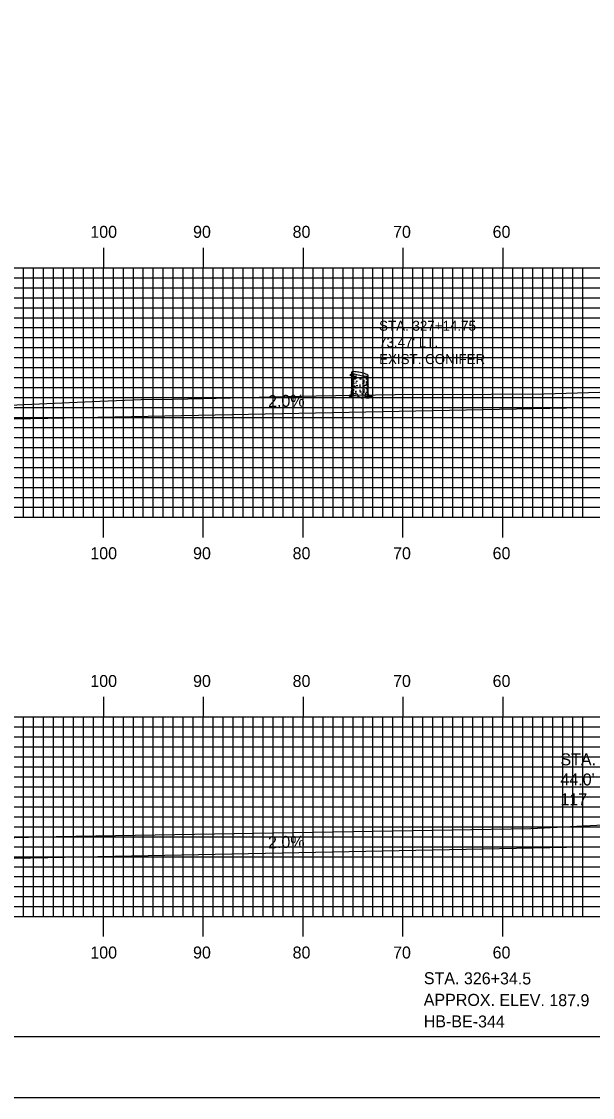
# Model space of a CAD drawing. Extents: x 1821605 to 1821948, y 442591 to 442811.
# Drawn here: x 1821662.5 to 1821719.7, y 442590.5 to 442698.3 of the extents above; entities that cross this region are included whole.
import ezdxf

# ---------------------------------------------------------------- set-up
doc = ezdxf.new("R2010")
doc.units = 0
for name, color, linetype in [('ANNOTATION', 7, 'Continuous'), ('BORDER', 7, 'Continuous'), ('BORING - NO REFUSAL', 7, 'Continuous'), ('D_Drainage_Text', 7, 'Continuous'), ('D_Text_Monospaced', 7, 'Continuous'), ('H_V ANNOTATION', 7, 'Continuous'), ('M_Trees_Conifer_Pay', 7, 'Continuous'), ('MAJOR', 7, 'Continuous'), ('MINOR', 7, 'Continuous'), ('PLOT BOUNDARY', 7, 'Continuous'), ('S_Roadway_Centerline', 7, 'Continuous')]:
    doc.layers.add(name, color=color, linetype=linetype)

msp = doc.modelspace()

# ---------------------------------------------------------------- linework, layer by layer
at = {"layer": 'ANNOTATION'}
for p, q in [((1821726.4, 442659.78), (1821630.74, 442657.87)), ((1821726.4, 442615.77), (1821630.74, 442613.85))]:
    msp.add_line(p, q, dxfattribs=at)
at = {"layer": 'BORDER'}
msp.add_lwpolyline([(1821621.14, 442596.67), (1821941.14, 442596.67), (1821941.14, 442806.67), (1821621.14, 442806.67)], close=True, dxfattribs=at)
at = {"layer": 'M_Trees_Conifer_Pay'}
for p, q in [((1821695.61, 442661.55), (1821695.61, 442663.2)), ((1821695.68, 442663.13), (1821695.68, 442662.97)), ((1821695.68, 442662.9), (1821695.68, 442662.77)), ((1821695.68, 442662.58), (1821695.68, 442662.25)), ((1821695.68, 442662.21), (1821695.68, 442662.05)), ((1821695.74, 442662.57), (1821695.79, 442662.51)), ((1821695.8, 442663.07), (1821695.8, 442662.85)), ((1821695.8, 442662.76), (1821695.8, 442662.71)), ((1821695.8, 442662.37), (1821695.8, 442662.24)), ((1821695.8, 442662.13), (1821695.8, 442662.02)), ((1821696.03, 442662.87), (1821696.03, 442662.67)), ((1821696.03, 442662.62), (1821696.03, 442662.53)), ((1821696.03, 442662.18), (1821696.03, 442662.07)), ((1821696.42, 442662.6), (1821696.42, 442662.5)), ((1821696.82, 442662.83), (1821696.82, 442662.66)), ((1821696.82, 442662.43), (1821696.82, 442662.19)), ((1821697.04, 442662.81), (1821697.04, 442662.58)), ((1821697.04, 442662.54), (1821697.04, 442662.46)), ((1821697.04, 442662.06), (1821697.04, 442661.92)), ((1821697.17, 442662.82), (1821697.17, 442662.72)), ((1821697.17, 442662.65), (1821697.17, 442662.44)), ((1821697.17, 442662.38), (1821697.17, 442662.18)), ((1821697.17, 442662.14), (1821697.17, 442661.8)), ((1821697.22, 442662.83), (1821697.22, 442662.36)), ((1821697.22, 442662.29), (1821697.22, 442661.99)), ((1821697.27, 442661.14), (1821697.27, 442662.87)), ((1821695.68, 442662), (1821695.68, 442661.79)), ((1821695.68, 442661.75), (1821695.68, 442661.68)), ((1821695.68, 442661.64), (1821695.68, 442661.47)), ((1821695.8, 442661.89), (1821695.8, 442661.74)), ((1821695.8, 442661.52), (1821695.8, 442661.34)), ((1821696.03, 442661.71), (1821696.03, 442661.56)), ((1821696.03, 442661.33), (1821696.03, 442661.24)), ((1821696.42, 442661.99), (1821696.42, 442661.91)), ((1821696.42, 442661.89), (1821696.42, 442661.74)), ((1821696.42, 442661.45), (1821696.42, 442661.29)), ((1821696.82, 442661.94), (1821696.82, 442661.79)), ((1821696.82, 442661.75), (1821696.82, 442661.58)), ((1821696.82, 442661.3), (1821696.82, 442661.14)), ((1821697.04, 442661.65), (1821697.04, 442661.51)), ((1821697.04, 442661.25), (1821697.04, 442661.15)), ((1821697.17, 442661.75), (1821697.17, 442661.61)), ((1821697.17, 442661.51), (1821697.17, 442661.13)), ((1821697.22, 442661.94), (1821697.22, 442661.45)), ((1821697.22, 442661.39), (1821697.22, 442661.14)), ((1821696.6, 442660.69), (1821696.73, 442660.75)), ((1821697.04, 442660.75), (1821696.88, 442660.82))]:
    msp.add_line(p, q, dxfattribs=at)
for points in [[(1821695.56, 442662.93), (1821695.49, 442662.94), (1821695.41, 442662.84)], [(1821695.79, 442662.7), (1821695.75, 442662.63), (1821695.71, 442662.68), (1821695.65, 442662.75), (1821695.56, 442662.94), (1821695.49, 442662.99), (1821695.46, 442663)], [(1821695.78, 442662.45), (1821695.74, 442662.57), (1821695.68, 442662.69), (1821695.65, 442662.76), (1821695.58, 442662.9)], [(1821695.82, 442662.66), (1821695.86, 442662.58), (1821695.86, 442662.51), (1821695.83, 442662.45)], [(1821697.09, 442662.17), (1821697.1, 442662.27), (1821697.06, 442662.24), (1821697.06, 442662.15)], [(1821695.61, 442661.55), (1821695.56, 442661.29), (1821695.54, 442661.02), (1821695.48, 442660.89), (1821695.35, 442660.86), (1821695.58, 442660.83), (1821695.58, 442660.83), (1821695.57, 442660.78), (1821695.32, 442660.68), (1821695.6, 442660.7), (1821695.95, 442660.72), (1821696.28, 442660.71), (1821696.27, 442660.79), (1821696.42, 442660.71), (1821696.6, 442660.69), (1821696.58, 442660.62), (1821696.85, 442660.66), (1821697.07, 442660.64), (1821697.36, 442660.65), (1821697.07, 442660.71), (1821697.04, 442660.75), (1821697.2, 442660.81), (1821697.44, 442660.82), (1821697.68, 442660.82), (1821697.34, 442660.88), (1821697.3, 442660.96), (1821697.27, 442661.14)], [(1821695.78, 442661.27), (1821695.71, 442661.16), (1821695.7, 442660.99), (1821695.58, 442660.83)], [(1821695.68, 442661.41), (1821695.68, 442661.27), (1821695.63, 442661.2), (1821695.62, 442661)], [(1821695.74, 442660.77), (1821695.75, 442660.91), (1821695.83, 442661.04)], [(1821695.95, 442661.77), (1821695.94, 442661.7), (1821695.89, 442661.71), (1821695.91, 442661.87)], [(1821696.02, 442661.16), (1821696.01, 442661.04), (1821695.93, 442660.99)], [(1821696.27, 442660.79), (1821696.19, 442660.93), (1821696.18, 442661.04)], [(1821696.76, 442660.86), (1821696.69, 442660.96), (1821696.66, 442661.1)], [(1821696.98, 442661.1), (1821696.98, 442660.97), (1821697.07, 442660.87)], [(1821697.15, 442661.08), (1821697.14, 442660.96), (1821697.19, 442660.87), (1821697.2, 442660.81)], [(1821697.22, 442661.1), (1821697.25, 442661.02), (1821697.27, 442660.93)]]:
    msp.add_lwpolyline(points, dxfattribs=at)
for centre, radius, start, end in [((1821695.63, 442663.2), 0.0264, 145.7806, 156.5926), ((1821695.64, 442663.2), 0.0314, 133.077, 145.7806), ((1821695.63, 442663.2), 0.0226, 156.5926, 168.2806), ((1821695.63, 442663.2), 0.0226, 168.2806, 179.9685), ((1821695.64, 442663.2), 0.0314, 190.7806, 203.4842), ((1821695.63, 442663.2), 0.0264, 179.9685, 190.7806), ((1821695.66, 442663.21), 0.0527, 203.4842, 213.2806), ((1821695.68, 442663.23), 0.0817, 213.2806, 227.6113), ((1821695.67, 442663.16), 0.0817, 108.9499, 123.2806), ((1821695.65, 442663.18), 0.0527, 123.2806, 133.077), ((1821695.8, 442663.35), 0.251, 227.6113, 235.7806), ((1821695.72, 442663), 0.251, 100.7806, 108.9499), ((1821696.11, 442663.81), 0.802, 235.7806, 251.9406), ((1821695.83, 442662.46), 0.802, 84.6206, 100.7806), ((1821695.42, 442658.1), 5.18, 78.2806, 84.6206), ((1821695.42, 442658.1), 5.18, 71.9406, 78.2806), ((1821695.65, 442663.08), 0.0441, 196.0515, 210), ((1821695.64, 442663.08), 0.0334, 185.7849, 196.0515), ((1821695.67, 442663.09), 0.0624, 210, 228.7494), ((1821695.64, 442662.92), 0.0334, 185.7849, 196.0515), ((1821695.65, 442662.92), 0.0441, 196.0515, 210), ((1821695.67, 442662.93), 0.0624, 210, 228.7494), ((1821695.64, 442662.48), 0.0334, 185.7849, 196.0515), ((1821695.64, 442662.24), 0.0334, 185.7849, 196.0515), ((1821695.65, 442662.24), 0.0441, 196.0515, 210), ((1821695.67, 442662.25), 0.0624, 210, 228.7494), ((1821695.64, 442662.03), 0.0334, 185.7849, 196.0515), ((1821695.65, 442662.03), 0.0441, 196.0515, 210), ((1821695.67, 442662.04), 0.0624, 210, 228.7494), ((1821695.74, 442663.17), 0.172, 228.7494, 240), ((1821695.74, 442663.02), 0.172, 228.7494, 240), ((1821695.74, 442662.34), 0.172, 228.7494, 240), ((1821695.94, 442663.36), 0.571, 240, 242.9763), ((1821695.94, 442662.68), 0.571, 240, 242.8104), ((1821695.94, 442662.92), 0.571, 242.9571, 255.5507), ((1821695.94, 442663.52), 0.571, 247.5868, 255.5683), ((1821695.94, 442662.68), 0.571, 253.0704, 261.8968), ((1821695.94, 442663.36), 0.571, 255.6333, 261.8968), ((1821697.46, 442667.97), 5.18, 251.9406, 258.2806), ((1821696.44, 442666.88), 4.12, 261.8968, 263.762), ((1821696.44, 442666.2), 4.12, 261.8968, 262.3875), ((1821696.44, 442666.65), 4.12, 262.9442, 264.2151), ((1821696.44, 442666.43), 4.12, 264.0496, 266.2948), ((1821697.46, 442667.97), 5.18, 258.2806, 264.6206), ((1821696.44, 442666.65), 4.12, 269.6419, 270), ((1821696.44, 442666.65), 4.12, 270, 271.9249), ((1821696.44, 442666.88), 4.12, 273.2669, 275.3045), ((1821696.44, 442666.2), 4.12, 273.3324, 275.919), ((1821697.05, 442663.61), 0.802, 264.6206, 280.7806), ((1821696.77, 442662.26), 0.802, 55.7806, 71.9406), ((1821696.94, 442663.13), 0.571, 282.0154, 293.1403), ((1821696.94, 442662.92), 0.571, 292.9413, 300), ((1821697.16, 442663.07), 0.251, 280.7806, 288.9499), ((1821697.08, 442662.72), 0.251, 47.6113, 55.7806), ((1821696.94, 442663.13), 0.571, 299.6633, 300), ((1821696.94, 442662.68), 0.571, 299.6633, 300), ((1821697.14, 442662.78), 0.172, 300, 311.2506), ((1821697.14, 442662.34), 0.172, 300, 311.2506), ((1821697.21, 442662.91), 0.0817, 288.9499, 303.2806), ((1821697.2, 442662.84), 0.0817, 33.2806, 47.6113), ((1821697.21, 442662.7), 0.0624, 311.2506, 330), ((1821697.21, 442662.25), 0.0624, 311.2506, 330), ((1821697.21, 442662.04), 0.0624, 311.2506, 330), ((1821697.24, 442662.87), 0.0314, 313.077, 325.7806), ((1821697.23, 442662.89), 0.0527, 303.2806, 313.077), ((1821697.22, 442662.86), 0.0527, 23.4842, 33.2806), ((1821697.24, 442662.87), 0.0314, 10.7806, 23.4842), ((1821697.25, 442662.87), 0.0264, 359.9685, 10.7806), ((1821697.25, 442662.87), 0.0226, 348.2806, 359.9685), ((1821697.25, 442662.87), 0.0226, 336.5926, 348.2806), ((1821697.25, 442662.87), 0.0264, 325.7806, 336.5926), ((1821697.24, 442662.69), 0.0334, 0, 16.0515), ((1821697.24, 442662.69), 0.0334, 343.9485, 360), ((1821697.23, 442662.69), 0.0441, 330, 343.9485), ((1821697.24, 442662.24), 0.0334, 0, 16.0515), ((1821697.24, 442662.24), 0.0334, 343.9485, 360), ((1821697.23, 442662.24), 0.0441, 330, 343.9485), ((1821697.24, 442662.03), 0.0334, 0, 16.0515), ((1821697.24, 442662.03), 0.0334, 343.9485, 360), ((1821697.23, 442662.03), 0.0441, 330, 343.9485), ((1821695.65, 442661.6), 0.0441, 196.0515, 210), ((1821695.64, 442661.6), 0.0334, 185.7849, 196.0515), ((1821695.67, 442661.61), 0.0624, 210, 228.7494), ((1821695.64, 442661.18), 0.0334, 185.7849, 196.0515), ((1821695.65, 442661.18), 0.0441, 196.0515, 210), ((1821695.67, 442661.19), 0.0624, 210, 228.7494), ((1821695.74, 442662.13), 0.172, 228.7494, 240), ((1821695.74, 442661.69), 0.172, 228.7494, 240), ((1821695.74, 442661.28), 0.172, 228.7494, 240), ((1821695.94, 442662.47), 0.571, 240, 242.8104), ((1821695.94, 442662.04), 0.571, 240, 250.7093), ((1821695.94, 442662.23), 0.571, 242.8104, 254.6017), ((1821695.94, 442661.84), 0.571, 242.7279, 251.4933), ((1821695.94, 442661.62), 0.571, 258.363, 261.8968), ((1821696.44, 442665.14), 4.12, 261.8968, 262.6316), ((1821696.44, 442665.36), 4.12, 263.2104, 264.2151), ((1821696.44, 442665.99), 4.12, 264.5431, 266.8507), ((1821696.44, 442665.99), 4.12, 269.6419, 270), ((1821696.44, 442665.36), 4.12, 269.8672, 270), ((1821696.44, 442665.36), 4.12, 270, 272.1883), ((1821696.44, 442665.75), 4.12, 273.6807, 275.284), ((1821696.44, 442665.55), 4.12, 274.1603, 276.5009), ((1821696.44, 442665.14), 4.12, 276.488, 277.5562), ((1821696.44, 442665.99), 4.12, 276.8526, 278.1032), ((1821696.94, 442662.47), 0.571, 278.1032, 280.7293), ((1821696.94, 442662.47), 0.571, 293.1403, 300), ((1821696.94, 442662.23), 0.571, 293.1403, 300), ((1821696.95, 442662.04), 0.571, 291.9732, 298.7631), ((1821696.94, 442661.84), 0.571, 293.1403, 300), ((1821696.94, 442661.62), 0.571, 295.4686, 300), ((1821697.14, 442662.13), 0.172, 300, 311.2506), ((1821697.14, 442661.89), 0.172, 300, 311.2506), ((1821697.14, 442661.5), 0.172, 300, 311.2506), ((1821697.14, 442661.28), 0.172, 300, 311.2506), ((1821697.21, 442661.81), 0.0624, 311.2506, 330), ((1821697.21, 442661.41), 0.0624, 311.2506, 330), ((1821697.21, 442661.19), 0.0624, 311.2506, 330), ((1821697.24, 442661.79), 0.0334, 0, 16.0515), ((1821697.24, 442661.79), 0.0334, 343.9485, 360), ((1821697.23, 442661.8), 0.0441, 330, 343.9485), ((1821697.24, 442661.6), 0.0334, 0, 16.0515), ((1821697.24, 442661.4), 0.0334, 0, 16.0515), ((1821697.24, 442661.4), 0.0334, 343.9485, 360), ((1821697.23, 442661.4), 0.0441, 330, 343.9485), ((1821697.24, 442661.18), 0.0334, 0, 16.0515), ((1821697.24, 442661.18), 0.0334, 343.9485, 360), ((1821697.23, 442661.18), 0.0441, 330, 343.9485)]:
    msp.add_arc(centre, radius, start, end, dxfattribs=at)
at = {"layer": 'MAJOR'}
for p, q in [((1821670.74, 442675.67), (1821670.74, 442673.67)), ((1821680.74, 442675.67), (1821680.74, 442673.67)), ((1821690.74, 442675.67), (1821690.74, 442673.67)), ((1821700.74, 442675.67), (1821700.74, 442673.67)), ((1821710.74, 442675.67), (1821710.74, 442673.67)), ((1821630.74, 442673.67), (1821910.74, 442673.67)), ((1821630.74, 442673.67), (1821910.74, 442673.67)), ((1821670.74, 442648.67), (1821670.74, 442673.67)), ((1821680.74, 442648.67), (1821680.74, 442673.67)), ((1821690.74, 442648.67), (1821690.74, 442673.67)), ((1821700.74, 442648.67), (1821700.74, 442673.67)), ((1821710.74, 442648.67), (1821710.74, 442673.67)), ((1821630.74, 442668.67), (1821910.74, 442668.67)), ((1821630.74, 442663.67), (1821910.74, 442663.67)), ((1821630.74, 442658.67), (1821910.74, 442658.67)), ((1821630.74, 442653.67), (1821910.74, 442653.67)), ((1821630.74, 442648.67), (1821910.74, 442648.67)), ((1821630.74, 442648.67), (1821910.74, 442648.67)), ((1821670.74, 442646.66), (1821670.74, 442648.67)), ((1821680.74, 442646.66), (1821680.74, 442648.67)), ((1821690.74, 442646.66), (1821690.74, 442648.67)), ((1821700.74, 442646.66), (1821700.74, 442648.67)), ((1821710.74, 442646.66), (1821710.74, 442648.67)), ((1821670.74, 442630.67), (1821670.74, 442628.67)), ((1821680.74, 442630.67), (1821680.74, 442628.67)), ((1821690.74, 442630.67), (1821690.74, 442628.67)), ((1821700.74, 442630.67), (1821700.74, 442628.67)), ((1821710.74, 442630.67), (1821710.74, 442628.67)), ((1821630.74, 442628.67), (1821910.74, 442628.67)), ((1821630.74, 442628.67), (1821910.74, 442628.67)), ((1821670.74, 442608.67), (1821670.74, 442628.67)), ((1821680.74, 442608.67), (1821680.74, 442628.67)), ((1821690.74, 442608.67), (1821690.74, 442628.67)), ((1821700.74, 442608.67), (1821700.74, 442628.67)), ((1821710.74, 442608.67), (1821710.74, 442628.67)), ((1821630.74, 442623.67), (1821910.74, 442623.67)), ((1821630.74, 442618.67), (1821910.74, 442618.67)), ((1821630.74, 442613.67), (1821910.74, 442613.67)), ((1821630.74, 442608.67), (1821910.74, 442608.67)), ((1821630.74, 442608.67), (1821910.74, 442608.67)), ((1821670.74, 442606.66), (1821670.74, 442608.67)), ((1821680.74, 442606.66), (1821680.74, 442608.67)), ((1821690.74, 442606.66), (1821690.74, 442608.67)), ((1821700.74, 442606.66), (1821700.74, 442608.67)), ((1821710.74, 442606.66), (1821710.74, 442608.67))]:
    msp.add_line(p, q, dxfattribs=at)
at = {"layer": 'MINOR'}
for p, q in [((1821662.74, 442648.67), (1821662.74, 442673.67)), ((1821663.74, 442648.67), (1821663.74, 442673.67)), ((1821664.74, 442648.67), (1821664.74, 442673.67)), ((1821665.74, 442648.67), (1821665.74, 442673.67)), ((1821666.74, 442648.67), (1821666.74, 442673.67)), ((1821667.74, 442648.67), (1821667.74, 442673.67)), ((1821668.74, 442648.67), (1821668.74, 442673.67)), ((1821669.74, 442648.67), (1821669.74, 442673.67)), ((1821671.74, 442648.67), (1821671.74, 442673.67)), ((1821672.74, 442648.67), (1821672.74, 442673.67)), ((1821673.74, 442648.67), (1821673.74, 442673.67)), ((1821674.74, 442648.67), (1821674.74, 442673.67)), ((1821675.74, 442648.67), (1821675.74, 442673.67)), ((1821676.74, 442648.67), (1821676.74, 442673.67)), ((1821677.74, 442648.67), (1821677.74, 442673.67)), ((1821678.74, 442648.67), (1821678.74, 442673.67)), ((1821679.74, 442648.67), (1821679.74, 442673.67)), ((1821681.74, 442648.67), (1821681.74, 442673.67)), ((1821682.74, 442648.67), (1821682.74, 442673.67)), ((1821683.74, 442648.67), (1821683.74, 442673.67)), ((1821684.74, 442648.67), (1821684.74, 442673.67)), ((1821685.74, 442648.67), (1821685.74, 442673.67)), ((1821686.74, 442648.67), (1821686.74, 442673.67)), ((1821687.74, 442648.67), (1821687.74, 442673.67)), ((1821688.74, 442648.67), (1821688.74, 442673.67)), ((1821689.74, 442648.67), (1821689.74, 442673.67)), ((1821691.74, 442648.67), (1821691.74, 442673.67)), ((1821692.74, 442648.67), (1821692.74, 442673.67)), ((1821693.74, 442648.67), (1821693.74, 442673.67)), ((1821694.74, 442648.67), (1821694.74, 442673.67)), ((1821695.74, 442648.67), (1821695.74, 442673.67)), ((1821696.74, 442648.67), (1821696.74, 442673.67)), ((1821697.74, 442648.67), (1821697.74, 442673.67)), ((1821698.74, 442648.67), (1821698.74, 442673.67)), ((1821699.74, 442648.67), (1821699.74, 442673.67)), ((1821701.74, 442648.67), (1821701.74, 442673.67)), ((1821702.74, 442648.67), (1821702.74, 442673.67)), ((1821703.74, 442648.67), (1821703.74, 442673.67)), ((1821704.74, 442648.67), (1821704.74, 442673.67)), ((1821705.74, 442648.67), (1821705.74, 442673.67)), ((1821706.74, 442648.67), (1821706.74, 442673.67)), ((1821707.74, 442648.67), (1821707.74, 442673.67)), ((1821708.74, 442648.67), (1821708.74, 442673.67)), ((1821709.74, 442648.67), (1821709.74, 442673.67)), ((1821711.74, 442648.67), (1821711.74, 442673.67)), ((1821712.74, 442648.67), (1821712.74, 442673.67)), ((1821713.74, 442648.67), (1821713.74, 442673.67)), ((1821714.74, 442648.67), (1821714.74, 442673.67)), ((1821715.74, 442648.67), (1821715.74, 442673.67)), ((1821716.74, 442648.67), (1821716.74, 442673.67)), ((1821717.74, 442648.67), (1821717.74, 442673.67)), ((1821718.74, 442648.67), (1821718.74, 442673.67)), ((1821630.74, 442672.67), (1821910.74, 442672.67)), ((1821630.74, 442671.67), (1821910.74, 442671.67)), ((1821630.74, 442670.67), (1821910.74, 442670.67)), ((1821630.74, 442669.67), (1821910.74, 442669.67)), ((1821630.74, 442667.67), (1821910.74, 442667.67)), ((1821630.74, 442666.67), (1821910.74, 442666.67)), ((1821630.74, 442665.67), (1821910.74, 442665.67)), ((1821630.74, 442664.67), (1821910.74, 442664.67)), ((1821630.74, 442662.67), (1821910.74, 442662.67)), ((1821630.74, 442661.67), (1821910.74, 442661.67)), ((1821630.74, 442660.67), (1821910.74, 442660.67)), ((1821630.74, 442659.67), (1821910.74, 442659.67)), ((1821630.74, 442657.67), (1821910.74, 442657.67)), ((1821630.74, 442656.67), (1821910.74, 442656.67)), ((1821630.74, 442655.67), (1821910.74, 442655.67)), ((1821630.74, 442654.67), (1821910.74, 442654.67)), ((1821630.74, 442652.67), (1821910.74, 442652.67)), ((1821630.74, 442651.67), (1821910.74, 442651.67)), ((1821630.74, 442650.67), (1821910.74, 442650.67)), ((1821630.74, 442649.67), (1821910.74, 442649.67)), ((1821662.74, 442608.67), (1821662.74, 442628.67)), ((1821663.74, 442608.67), (1821663.74, 442628.67)), ((1821664.74, 442608.67), (1821664.74, 442628.67)), ((1821665.74, 442608.67), (1821665.74, 442628.67)), ((1821666.74, 442608.67), (1821666.74, 442628.67)), ((1821667.74, 442608.67), (1821667.74, 442628.67)), ((1821668.74, 442608.67), (1821668.74, 442628.67)), ((1821669.74, 442608.67), (1821669.74, 442628.67)), ((1821671.74, 442608.67), (1821671.74, 442628.67)), ((1821672.74, 442608.67), (1821672.74, 442628.67)), ((1821673.74, 442608.67), (1821673.74, 442628.67)), ((1821674.74, 442608.67), (1821674.74, 442628.67)), ((1821675.74, 442608.67), (1821675.74, 442628.67)), ((1821676.74, 442608.67), (1821676.74, 442628.67)), ((1821677.74, 442608.67), (1821677.74, 442628.67)), ((1821678.74, 442608.67), (1821678.74, 442628.67)), ((1821679.74, 442608.67), (1821679.74, 442628.67)), ((1821681.74, 442608.67), (1821681.74, 442628.67)), ((1821682.74, 442608.67), (1821682.74, 442628.67)), ((1821683.74, 442608.67), (1821683.74, 442628.67)), ((1821684.74, 442608.67), (1821684.74, 442628.67)), ((1821685.74, 442608.67), (1821685.74, 442628.67)), ((1821686.74, 442608.67), (1821686.74, 442628.67)), ((1821687.74, 442608.67), (1821687.74, 442628.67)), ((1821688.74, 442608.67), (1821688.74, 442628.67)), ((1821689.74, 442608.67), (1821689.74, 442628.67)), ((1821691.74, 442608.67), (1821691.74, 442628.67)), ((1821692.74, 442608.67), (1821692.74, 442628.67)), ((1821693.74, 442608.67), (1821693.74, 442628.67)), ((1821694.74, 442608.67), (1821694.74, 442628.67)), ((1821695.74, 442608.67), (1821695.74, 442628.67)), ((1821696.74, 442608.67), (1821696.74, 442628.67)), ((1821697.74, 442608.67), (1821697.74, 442628.67)), ((1821698.74, 442608.67), (1821698.74, 442628.67)), ((1821699.74, 442608.67), (1821699.74, 442628.67)), ((1821701.74, 442608.67), (1821701.74, 442628.67)), ((1821702.74, 442608.67), (1821702.74, 442628.67)), ((1821703.74, 442608.67), (1821703.74, 442628.67)), ((1821704.74, 442608.67), (1821704.74, 442628.67)), ((1821705.74, 442608.67), (1821705.74, 442628.67)), ((1821706.74, 442608.67), (1821706.74, 442628.67)), ((1821707.74, 442608.67), (1821707.74, 442628.67)), ((1821708.74, 442608.67), (1821708.74, 442628.67)), ((1821709.74, 442608.67), (1821709.74, 442628.67)), ((1821711.74, 442608.67), (1821711.74, 442628.67)), ((1821712.74, 442608.67), (1821712.74, 442628.67)), ((1821713.74, 442608.67), (1821713.74, 442628.67)), ((1821714.74, 442608.67), (1821714.74, 442628.67)), ((1821715.74, 442608.67), (1821715.74, 442628.67)), ((1821716.74, 442608.67), (1821716.74, 442628.67)), ((1821717.74, 442608.67), (1821717.74, 442628.67)), ((1821718.74, 442608.67), (1821718.74, 442628.67)), ((1821630.74, 442627.67), (1821910.74, 442627.67)), ((1821630.74, 442626.67), (1821910.74, 442626.67)), ((1821630.74, 442625.67), (1821910.74, 442625.67)), ((1821630.74, 442624.67), (1821910.74, 442624.67)), ((1821630.74, 442622.67), (1821910.74, 442622.67)), ((1821630.74, 442621.67), (1821910.74, 442621.67)), ((1821630.74, 442620.67), (1821910.74, 442620.67)), ((1821630.74, 442619.67), (1821910.74, 442619.67)), ((1821630.74, 442617.67), (1821910.74, 442617.67)), ((1821630.74, 442616.67), (1821910.74, 442616.67)), ((1821630.74, 442615.67), (1821910.74, 442615.67)), ((1821630.74, 442614.67), (1821910.74, 442614.67)), ((1821630.74, 442612.67), (1821910.74, 442612.67)), ((1821630.74, 442611.67), (1821910.74, 442611.67)), ((1821630.74, 442610.67), (1821910.74, 442610.67)), ((1821630.74, 442609.67), (1821910.74, 442609.67))]:
    msp.add_line(p, q, dxfattribs=at)
at = {"layer": 'PLOT BOUNDARY'}
msp.add_lwpolyline([(1821604.96, 442590.55), (1821944.96, 442590.55), (1821944.96, 442810.55), (1821604.96, 442810.55)], close=True, dxfattribs=at)
at = {"layer": 'S_Roadway_Centerline'}
for points in [[(1821630.74, 442658.31), (1821641.95, 442659.06), (1821654.31, 442659.67), (1821658.52, 442659.83), (1821661.29, 442659.89), (1821670.37, 442660.31), (1821674.52, 442660.46), (1821677.77, 442660.52), (1821692.04, 442660.84), (1821699.95, 442660.98), (1821709.59, 442660.99), (1821714.85, 442661.05), (1821726.06, 442661.38)], [(1821630.74, 442614.78), (1821645.15, 442615.72), (1821653.89, 442616.35), (1821656.34, 442616.45), (1821666.02, 442616.68), (1821713.55, 442617.48), (1821722.12, 442617.92)]]:
    msp.add_lwpolyline(points, dxfattribs=at)

# ---------------------------------------------------------------- texts
at = {"layer": 'ANNOTATION'}
for p in [(1821687.24, 442659.7), (1821687.24, 442615.51)]:
    msp.add_text('2.0%', height=1.2, rotation=1.1458, dxfattribs=at).set_placement(p)
at = {"layer": 'BORING - NO REFUSAL'}
for s, p in [('STA. 326+34.5', (1821702.83, 442601.9)), ('APPROX. ELEV. 187.9', (1821702.82, 442599.74)), ('HB-BE-344', (1821702.82, 442597.58))]:
    msp.add_text(s, height=1.2, rotation=359.8142, dxfattribs=at).set_placement(p)
at = {"layer": 'D_Drainage_Text'}
for s, p in [('STA. 326+25.00', (1821716.51, 442623.82)), ("44.0' LT", (1821716.51, 442621.81)), ('117', (1821716.51, 442619.81))]:
    msp.add_text(s, height=1.2, dxfattribs=at).set_placement(p)
at = {"layer": 'D_Text_Monospaced'}
for s, p in [('STA. 327+14.75', (1821698.35, 442667.36)), ("73.47' LT.", (1821698.35, 442665.7)), ('EXIST. CONIFER', (1821698.35, 442664.02))]:
    msp.add_text(s, height=1, dxfattribs=at).set_placement(p)
at = {"layer": 'H_V ANNOTATION'}
for s, p in [('100', (1821669.43, 442676.67)), ('90', (1821679.72, 442676.67)), ('80', (1821689.69, 442676.67)), ('70', (1821699.75, 442676.67)), ('60', (1821709.72, 442676.67)), ('100', (1821669.43, 442644.47)), ('90', (1821679.72, 442644.47)), ('80', (1821689.69, 442644.47)), ('70', (1821699.75, 442644.47)), ('60', (1821709.72, 442644.47)), ('100', (1821669.43, 442631.67)), ('90', (1821679.72, 442631.67)), ('80', (1821689.69, 442631.67)), ('70', (1821699.75, 442631.67)), ('60', (1821709.72, 442631.67)), ('100', (1821669.43, 442604.47)), ('90', (1821679.72, 442604.47)), ('80', (1821689.69, 442604.47)), ('70', (1821699.75, 442604.47)), ('60', (1821709.72, 442604.47))]:
    msp.add_text(s, height=1.2, dxfattribs=at).set_placement(p)

doc.saveas('drawing.dxf')
